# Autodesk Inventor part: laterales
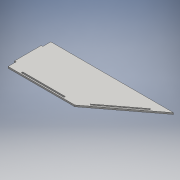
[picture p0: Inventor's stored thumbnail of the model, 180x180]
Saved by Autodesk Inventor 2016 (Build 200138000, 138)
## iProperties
Created: 2016-06
Part Number: laterales
Material: Genérico
Document SubType Name: Modeling
Designer: adm
Density: 1 g/cm^3
Appearance: Valor por defecto
Author: adm
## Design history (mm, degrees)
sketch "Boceto1"
  geometry: L1 (-111.459, -111.872)-(13.541, -111.872); L2 (118.541, -31.872)-(-111.459, -31.872); L3 (118.541, -31.872)-(13.541, -111.872); L4 (-111.459, -46.872)-(-114.459, -46.872); L5 (-111.459, -96.872)-(-114.459, -96.872); L6 (-111.459, -31.872)-(-111.459, -46.872); L7 (-111.459, -96.872)-(-111.459, -111.872); L8 (-114.459, -46.872)-(-114.459, -96.872); L9 (28.329, -97.679)-(92.069, -49.115); L10 (26.704, -95.546)-(90.444, -46.982); L11 (26.704, -95.546)-(28.329, -97.679); L12 (90.444, -46.982)-(92.069, -49.115); L13 (-111.459, -96.872)-(-111.459, -111.872); L14 (-49, -107)-(-49, -111.872); L15 (-89, -107)-(-89, -109.872); L16 (-9, -107)-(-9, -109.872); L17 (-89, -107)-(-9, -107); L18 (-89, -109.872)-(-9, -109.872); 3 further points
  constraints: 36 end point, 8 parallel, 2 horizontal, 2 midpoint, 2 perpendicular, 1 point on line, 1 vertical
  dimensions: "d0" = 230 distance of L2.start L2.end; "d1" = 80 distance between parallel lines of L1 L2; "d2" = 15 distance between parallel lines of L5 L1; "d3" = 50 distance between parallel lines of L4 L5; "d4" = 3 distance of L4.start L4.end; "d6" = 3 distance from line of L5.end L7; "d7" = 2.32705 distance between parallel lines of L3 L9; "d8" = 2.68119 distance between parallel lines of L9 L10; "d12" = 80.13217 distance between parallel lines of L11 L12; "d15" = 125 distance from line of L1.end L13; "d16" = 62.45937 distance between parallel lines of L13 L14; "d17" = 40 distance between parallel lines of L14 L15; "d18" = 40 distance between parallel lines of L14 L16
extrude "Extrusión1" new body sketch "Boceto1" distance "d19" = 3; taper "d20" = 0 deg
node "Sólido1"
other parameters: "d13" = 2, "d14" = 2.87174
